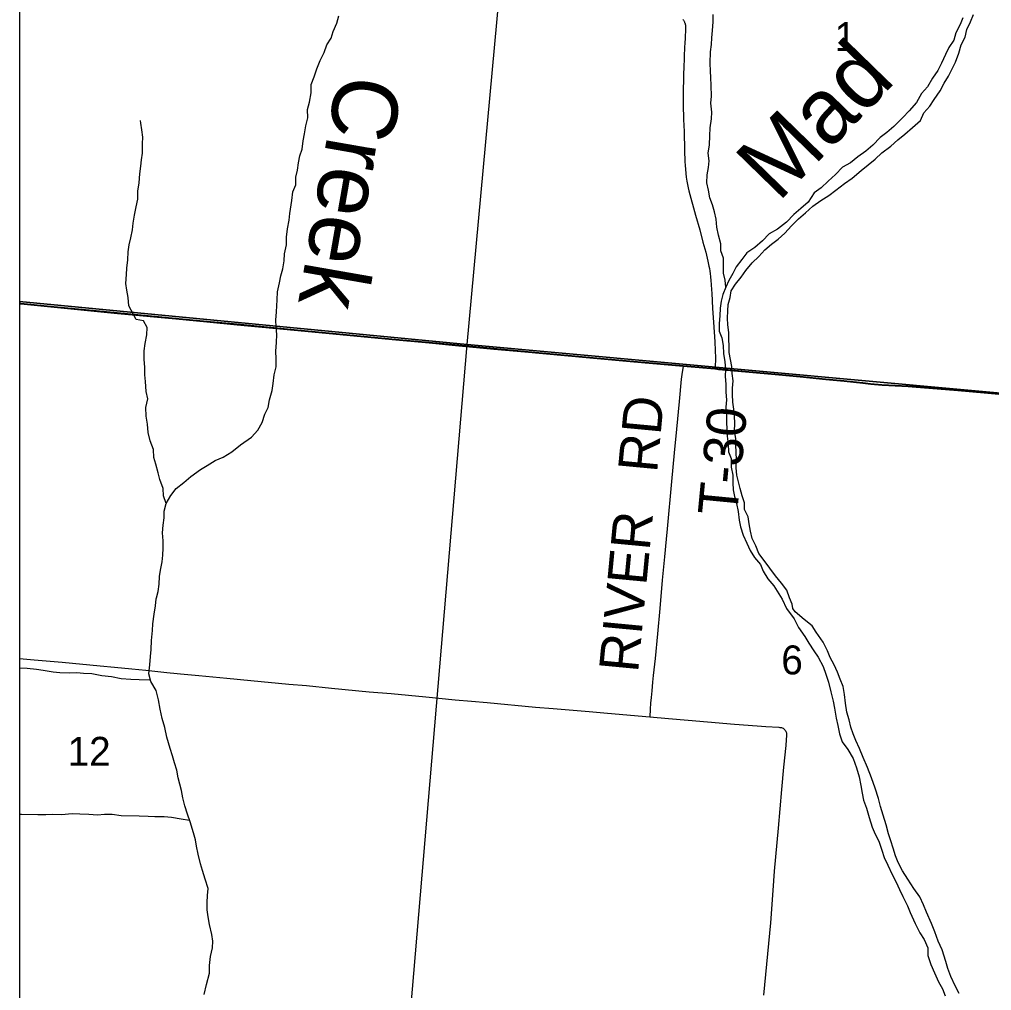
# Model space of a CAD drawing. Extents: x 0 to 1067, y 0 to 440.
# Drawn here: x 798.04 to 799.446, y 352.868 to 354.272 of the extents above; entities that cross this region are included whole.
import ezdxf

# ---------------------------------------------------------------- set-up
doc = ezdxf.new("R2010")
doc.units = 0
for name, color, linetype in [('GM_X_County_Road', 7, 'Continuous'), ('GM_X_Major_River', 7, 'Continuous'), ('GM_X_Major_River_Text', 7, 'Continuous'), ('GM_X_Minor_River', 7, 'Continuous'), ('GM_X_Minor_River_Text', 7, 'Continuous'), ('GM_X_Section', 7, 'Continuous'), ('GM_X_Section_Text', 7, 'Continuous'), ('GM_X_Township_Road', 7, 'Continuous'), ('GM_X_Township_Road_Text', 7, 'Continuous'), ('GM_X_US_Shield', 7, 'Continuous')]:
    doc.layers.add(name, color=color, linetype=linetype)

msp = doc.modelspace()

# ---------------------------------------------------------------- linework, layer by layer
at = {"layer": 'GM_X_County_Road'}
msp.add_line((799.0005, 353.7711), (799.0462, 353.7669), dxfattribs=at)
for points in [[(798.0401, 353.8611), (798.0422, 353.8609), (798.0903, 353.8562), (798.1819, 353.8473), (798.2663, 353.8393), (798.3114, 353.835), (798.3551, 353.8309), (798.4377, 353.8232), (798.5792, 353.8095), (798.6328, 353.8046), (798.6708, 353.8011), (798.7265, 353.7958), (798.7713, 353.7915), (798.8599, 353.7837), (798.9236, 353.7778), (799.0005, 353.7711)], [(799.0462, 353.7669), (799.0514, 353.7664), (799.0903, 353.7628), (799.1386, 353.7583), (799.1695, 353.7554), (799.2066, 353.7518), (799.2331, 353.7491), (799.2604, 353.7462), (799.2719, 353.7448), (799.2881, 353.7435), (799.326, 353.7415), (799.3372, 353.7408), (799.3978, 353.7359), (799.4356, 353.7325), (799.5049, 353.7264), (799.5507, 353.7223), (799.6243, 353.7157), (799.6485, 353.7137), (799.6868, 353.7102), (799.7019, 353.7088)]]:
    msp.add_lwpolyline(points, dxfattribs=at)
at = {"layer": 'GM_X_Major_River'}
for points in [[(799.1588, 353.4205), (799.1579, 353.4267), (799.1542, 353.436), (799.1502, 353.4472), (799.1425, 353.4573), (799.1337, 353.4679), (799.1257, 353.4788), (799.1173, 353.4901), (799.11, 353.5002), (799.1054, 353.5114), (799.1004, 353.5218), (799.0977, 353.5326), (799.0957, 353.5429), (799.0945, 353.5529), (799.0891, 353.5637), (799.089, 353.5736), (799.0859, 353.5836), (799.0828, 353.594), (799.078, 353.6132), (799.0768, 353.6239), (799.0775, 353.6356), (799.0771, 353.6467), (799.0763, 353.6566), (799.0765, 353.6665), (799.0746, 353.6772), (799.0749, 353.6883), (799.0748, 353.6993), (799.0736, 353.7089), (799.072, 353.7188), (799.0716, 353.7299), (799.0715, 353.7394), (799.0725, 353.7497), (799.0713, 353.7604), (799.0709, 353.7707), (799.0669, 353.7906), (799.0668, 353.8001), (799.0663, 353.81), (799.0666, 353.8195), (799.065, 353.8306), (799.0645, 353.8402), (799.0648, 353.8508), (799.0655, 353.8603), (799.0681, 353.8701), (799.0699, 353.88), (799.0759, 353.8897), (799.0841, 353.8997), (799.0912, 353.9094), (799.1003, 353.9206), (799.11, 353.9294), (799.1183, 353.939), (799.128, 353.9475), (799.1377, 353.9548), (799.1474, 353.9633), (799.1569, 353.9737), (799.1674, 353.984), (799.1771, 353.9928), (799.1877, 354.0024), (799.1993, 354.0104), (799.2109, 354.0177), (799.221, 354.0254), (799.2338, 354.0353), (799.245, 354.0426), (799.2579, 354.054), (799.268, 354.062), (799.2781, 354.0705), (799.2878, 354.0793), (799.3006, 354.0892), (799.3111, 354.0984), (799.3212, 354.1065), (799.3321, 354.1161), (799.3435, 354.1264), (799.3487, 354.1373), (799.357, 354.1469), (799.3637, 354.1566), (799.372, 354.1689), (799.378, 354.1802), (799.384, 354.1903), (799.3945, 354.2105), (799.399, 354.2237), (799.4024, 354.2354), (799.4081, 354.2467), (799.4107, 354.258), (799.4159, 354.2689), (799.4204, 354.2794)], [(799.4051, 354.2746), (799.401, 354.2648), (799.395, 354.2532), (799.392, 354.2426), (799.3845, 354.2318), (799.38, 354.2216), (799.374, 354.2092), (799.3687, 354.1984), (799.3612, 354.1875), (799.3536, 354.1748), (799.3453, 354.1652), (799.3378, 354.1521), (799.3272, 354.1402), (799.3182, 354.1306), (799.3049, 354.1173), (799.2951, 354.1088), (799.2854, 354.1015), (799.2745, 354.0904), (799.2644, 354.082), (799.2531, 354.0735), (799.2422, 354.0651), (799.2307, 354.0586), (799.2209, 354.0482), (799.21, 354.0383), (799.1998, 354.0287), (799.1901, 354.0218), (799.1814, 354.0083), (799.1705, 353.9991), (799.1604, 353.9903), (799.1498, 353.9792), (799.137, 353.9689), (799.125, 353.9621), (799.1152, 353.9521), (799.104, 353.9425), (799.0923, 353.9349), (799.0852, 353.9252), (799.077, 353.9148), (799.0721, 353.905), (799.0665, 353.8949), (799.0621, 353.8852), (799.0576, 353.8746), (799.0554, 353.8648), (799.054, 353.855), (799.0533, 353.8436), (799.0522, 353.8329), (799.0526, 353.8215), (799.0565, 353.8118), (799.0581, 353.8008), (799.0589, 353.7893), (799.0608, 353.7771), (799.0616, 353.7664), (799.061, 353.7565), (799.0621, 353.7443), (799.0622, 353.7336), (799.063, 353.7225), (799.0623, 353.7115), (799.0631, 353.6997), (799.0632, 353.6902), (799.0641, 353.6696), (799.0653, 353.6581), (799.0657, 353.647), (799.07, 353.6374), (799.0696, 353.6248), (799.072, 353.6133), (799.0724, 353.6023), (799.0729, 353.5924), (799.0748, 353.5824), (799.0776, 353.5724), (799.0799, 353.5609), (799.0814, 353.5483), (799.0834, 353.5387), (799.0873, 353.5268), (799.0926, 353.5152), (799.0972, 353.5044), (799.1034, 353.4943), (799.1122, 353.4842), (799.1161, 353.4745), (799.123, 353.4636), (799.1314, 353.4535), (799.1438, 353.4341), (799.1499, 353.4206)], [(799.1499, 353.4206), (799.1607, 353.4058), (799.1673, 353.3931), (799.1762, 353.38), (799.1821, 353.3704), (799.1892, 353.3596), (799.1958, 353.35), (799.2028, 353.3369), (799.2068, 353.3258), (799.2104, 353.3143), (799.214, 353.3002), (799.2172, 353.2868), (799.2193, 353.2765), (799.2217, 353.262), (799.2241, 353.2513), (799.2266, 353.2395), (799.2306, 353.228), (799.2384, 353.2169), (799.2461, 353.2038), (799.2512, 353.1904), (799.2548, 353.1774), (799.2572, 353.1648), (799.2593, 353.1534), (799.2614, 353.1434), (799.2654, 353.1319), (799.2693, 353.1186), (799.2736, 353.1044), (799.278, 353.0944), (799.2832, 353.0841), (799.2879, 353.0711), (799.2911, 353.0607), (799.2962, 353.0496), (799.3025, 353.0362), (799.3087, 353.0247), (799.3131, 353.0143), (799.3179, 353.004), (799.3249, 352.9905), (799.3289, 352.981), (799.3362, 352.9652), (799.3428, 352.9518), (799.3491, 352.9418), (799.3542, 352.9299), (799.3544, 352.9189), (799.3588, 352.9059), (799.3639, 352.8936), (799.3697, 352.881), (799.3756, 352.8706), (799.3793, 352.8603)], [(799.1625, 353.4157), (799.1588, 353.4205)], [(799.3995, 352.8641), (799.394, 352.8748), (799.3874, 352.8886), (799.383, 352.9001), (799.3802, 352.9101), (799.3751, 352.9269), (799.3693, 352.9395), (799.3646, 352.9533), (799.3598, 352.9652), (799.3525, 352.9813), (799.3478, 352.992), (799.3426, 353.0035), (799.3341, 353.0155), (799.3256, 353.0293), (799.3178, 353.0412), (799.3116, 353.0535), (799.3075, 353.0631), (799.3043, 353.0742), (799.3007, 353.0845), (799.2975, 353.0949), (799.2939, 353.1079), (799.2896, 353.122), (799.286, 353.1342), (799.2828, 353.1457), (799.2781, 353.1606), (799.273, 353.1759), (799.2672, 353.1905), (799.2606, 353.2051), (799.2555, 353.2181), (799.25, 353.2296), (799.2464, 353.2395), (799.2431, 353.2491), (799.2403, 353.2594), (799.237, 353.2705), (799.2354, 353.2839), (799.2337, 353.2961), (799.2316, 353.3079), (799.2276, 353.3186), (799.2236, 353.3286), (799.2189, 353.3389), (799.213, 353.3497), (799.209, 353.3596), (799.2027, 353.3719), (799.1926, 353.3864), (799.1869, 353.3954), (799.1756, 353.4049), (799.1625, 353.4157)]]:
    msp.add_lwpolyline(points, dxfattribs=at)
at = {"layer": 'GM_X_Minor_River'}
for points in [[(798.2379, 353.4345), (798.2384, 353.4359), (798.2406, 353.4454), (798.2424, 353.456), (798.2427, 353.4667), (798.2441, 353.4762), (798.2464, 353.4883), (798.2474, 353.4978), (798.2481, 353.508), (798.248, 353.5183), (798.2472, 353.5301), (798.2479, 353.5412), (798.2494, 353.5518), (798.2493, 353.5613), (798.2523, 353.5726), (798.259, 353.5839), (798.2669, 353.5943), (798.2778, 353.6027), (798.2879, 353.6115), (798.3019, 353.6214), (798.3119, 353.6272), (798.3235, 353.6348), (798.3347, 353.6394), (798.3474, 353.6471), (798.3599, 353.6573), (798.3757, 353.6683), (798.3851, 353.6786), (798.3915, 353.6895), (798.3949, 353.7016), (798.3998, 353.7113), (798.402, 353.7223), (798.4058, 353.7359), (798.4072, 353.7461), (798.4087, 353.7583), (798.4113, 353.77), (798.4117, 353.7814), (798.4112, 353.7925), (798.412, 353.8054), (798.4123, 353.8168), (798.4115, 353.8279), (798.411, 353.8374), (798.4118, 353.8496), (798.413, 353.8671), (798.4137, 353.8785), (798.4164, 353.8913), (798.4182, 353.9015), (798.4212, 353.9117), (798.423, 353.9231), (798.4237, 353.9334), (798.4263, 353.9462), (798.4267, 353.9576), (798.4278, 353.9694), (798.4304, 353.9823), (798.4315, 353.9918), (798.4343, 354.0103), (798.4358, 354.0232), (798.4399, 354.033), (798.4402, 354.0444), (798.4424, 354.0546), (798.4438, 354.0649), (798.4457, 354.0751), (798.449, 354.0849), (798.4508, 354.0967), (798.4527, 354.1069), (798.4545, 354.1186), (798.4575, 354.1303), (798.4571, 354.1422), (798.4597, 354.1527), (798.462, 354.1664), (798.4623, 354.1785), (798.4665, 354.1895), (798.4702, 354.2011), (798.4751, 354.2128), (798.4808, 354.2244), (798.4849, 354.2354), (798.4909, 354.2451), (798.4942, 354.2549), (798.4991, 354.2669), (798.5024, 354.2775)], [(799.0621, 353.8852), (799.0612, 353.8951), (799.0585, 353.9055), (799.0588, 353.9165), (799.0587, 353.9272), (799.0549, 353.9379), (799.0548, 353.9478), (799.0514, 353.9605), (799.049, 353.972), (799.0479, 353.9835), (799.0455, 353.9942), (799.0428, 354.0042), (799.0389, 354.0146), (799.0369, 354.0253), (799.0346, 354.036), (799.0353, 354.0478), (799.0368, 354.0584), (799.0378, 354.0679), (799.0366, 354.079), (799.0385, 354.0911), (799.0389, 354.1041), (799.0396, 354.1155), (799.0411, 354.1288), (799.0417, 354.1383), (799.0406, 354.1512), (799.0413, 354.1615), (799.041, 354.1767), (799.0405, 354.1882), (799.0401, 354.1977), (799.0393, 354.2092), (799.0401, 354.2255), (799.0412, 354.2361), (799.0418, 354.2456), (799.0429, 354.2563), (799.0437, 354.2688), (799.0436, 354.2795)], [(798.2523, 353.5726), (798.2484, 353.5834), (798.248, 353.5941), (798.243, 353.6072), (798.2407, 353.6168), (798.2376, 353.6294), (798.2345, 353.6391), (798.234, 353.6505), (798.2291, 353.6632), (798.2264, 353.6751), (798.2256, 353.6873), (798.2237, 353.6988), (798.2229, 353.711), (798.2259, 353.7239), (798.2236, 353.7346), (798.2225, 353.7487), (798.2213, 353.7583), (798.2216, 353.7697), (798.2204, 353.7808), (798.2204, 353.7933), (798.2222, 353.8036), (798.2245, 353.8161), (798.2248, 353.8267), (798.2197, 353.8364), (798.2092, 353.8386), (798.1984, 353.858), (798.1976, 353.8702), (798.1956, 353.8809), (798.194, 353.8905), (798.1951, 353.9034), (798.1954, 353.9129), (798.1969, 353.9247), (798.1972, 353.9365), (798.1987, 353.9463), (798.2012, 353.9565), (798.2035, 353.9679), (798.2045, 353.9777), (798.2064, 353.9891), (798.209, 354.0012), (798.2112, 354.0126), (798.2112, 354.024), (798.2134, 354.0361), (798.2142, 354.049), (798.2156, 354.06), (798.2167, 354.0695), (798.2181, 354.079), (798.2181, 354.0923), (798.2188, 354.1022), (798.2172, 354.1129), (798.2156, 354.1225), (798.2153, 354.1263)], [(798.2328, 353.3889), (798.2333, 353.3984), (798.2351, 353.4124), (798.2368, 353.4245), (798.2379, 353.4345)], [(798.3074, 352.8624), (798.3107, 352.8771), (798.3151, 352.8934), (798.3153, 352.9044), (798.3163, 352.9173), (798.3192, 352.9298), (798.3198, 352.9396), (798.3184, 352.9491), (798.3149, 352.9636), (798.3132, 352.9747), (798.3118, 352.985), (798.3116, 352.9956), (798.3122, 353.0058), (798.3131, 353.0157), (798.3088, 353.0294), (798.3049, 353.0417), (798.302, 353.0516), (798.2988, 353.0653), (798.2964, 353.0768), (798.2946, 353.0863), (798.2918, 353.0962), (798.2871, 353.1119), (798.2831, 353.1233), (798.2792, 353.1352), (798.2767, 353.147), (798.2746, 353.1576), (798.27, 353.1756), (798.2679, 353.1866), (798.2643, 353.1973), (798.2618, 353.2076), (798.2582, 353.2183), (798.2532, 353.2347), (798.2504, 353.2484), (798.2468, 353.2614), (798.2437, 353.2751), (798.2413, 353.2885), (798.2377, 353.3018), (798.2303, 353.3149), (798.2275, 353.3263), (798.2289, 353.3392), (798.2298, 353.3513), (798.2308, 353.3612), (798.2314, 353.3741), (798.2328, 353.3889)], [(798.2299, 353.3168), (798.2133, 353.3174), (798.2012, 353.318), (798.1875, 353.319), (798.1735, 353.3216), (798.1591, 353.323), (798.1447, 353.3259), (798.133, 353.3268), (798.1231, 353.3274), (798.1125, 353.3272), (798.0988, 353.3274), (798.089, 353.3287), (798.0746, 353.3309), (798.0648, 353.3326), (798.0515, 353.3336), (798.0401, 353.3344)], [(798.2863, 353.1142), (798.2743, 353.1159), (798.2603, 353.1184), (798.2497, 353.1193), (798.236, 353.1192), (798.2265, 353.1198), (798.2132, 353.1204), (798.1874, 353.1208), (798.1742, 353.1226), (798.1632, 353.1228), (798.1533, 353.1218), (798.1404, 353.1228), (798.1275, 353.1234), (798.1165, 353.1236), (798.1009, 353.1223), (798.0884, 353.1225), (798.0782, 353.1223), (798.0668, 353.1222), (798.0429, 353.1226), (798.0401, 353.1229)]]:
    msp.add_lwpolyline(points, dxfattribs=at)
at = {"layer": 'GM_X_Section'}
for points in [[(798.781, 354.8126), (799.7802, 354.7186), (799.6925, 353.7106), (798.688, 353.8024)], [(798.688, 353.8024), (799.6925, 353.7106), (799.6121, 352.7044), (798.6013, 352.7849)]]:
    msp.add_lwpolyline(points, close=True, dxfattribs=at)
at = {"layer": 'GM_X_Township_Road'}
msp.add_line((799.0462, 353.7669), (799.0005, 353.7711), dxfattribs=at)
for points in [[(798.0401, 357.6021), (798.0401, 353.8616), (798.042, 353.8615), (798.0901, 353.8568), (798.1817, 353.8479), (798.2661, 353.8398), (798.3111, 353.8356), (798.3549, 353.8315), (798.4375, 353.8237), (798.5789, 353.8101), (798.6326, 353.8052), (798.6706, 353.8016), (798.7262, 353.7963), (798.771, 353.7921), (798.8597, 353.7842), (798.9234, 353.7784), (799.0003, 353.7716), (799.0459, 353.7674), (799.0512, 353.7669), (799.0901, 353.7633), (799.1383, 353.7588), (799.1693, 353.756), (799.2063, 353.7523), (799.2329, 353.7496), (799.2601, 353.7467), (799.2716, 353.7454), (799.2879, 353.7441), (799.3258, 353.742), (799.3369, 353.7414), (799.3976, 353.7364), (799.4354, 353.7331), (799.5047, 353.7269)], [(798.9997, 354.2723), (799.0003, 354.2718), (799.0008, 354.2712), (799.0013, 354.2705), (799.0017, 354.2698), (799.0021, 354.269), (799.0025, 354.2681), (799.0028, 354.2672), (799.0032, 354.2662), (799.0034, 354.2653), (799.0036, 354.2641), (799.0036, 354.263), (799.0037, 354.2618), (799.0038, 354.2591), (799.0037, 354.2553), (799.0034, 354.2487), (799.0032, 354.2439), (799.0029, 354.2396), (799.0024, 354.231), (799.0019, 354.2201), (799.0017, 354.214), (799.0014, 354.2054), (799.0009, 354.1913), (799.0006, 354.1821), (799.0004, 354.1741), (799.0003, 354.1649), (799.0004, 354.1494), (799.0009, 354.1277), (799.0016, 354.1103), (799.0024, 354.083), (799.0029, 354.0668), (799.0033, 354.0613), (799.0037, 354.0557), (799.0043, 354.0498), (799.0049, 354.0445), (799.0058, 354.0387), (799.0067, 354.0335), (799.0077, 354.0288), (799.0087, 354.0244), (799.0184, 353.9894), (799.0244, 353.9679), (799.0289, 353.9505), (799.033, 353.9358), (799.036, 353.923), (799.0366, 353.9203), (799.0377, 353.9154), (799.0384, 353.912), (799.0391, 353.9085), (799.0396, 353.9048), (799.0401, 353.9), (799.0405, 353.8949), (799.0409, 353.8892), (799.0414, 353.8814), (799.0416, 353.8766), (799.0428, 353.8546), (799.0441, 353.8345), (799.046, 353.8064), (799.0464, 353.7938), (799.0469, 353.783), (799.047, 353.7805), (799.0469, 353.7772), (799.0467, 353.7744), (799.0465, 353.7721), (799.0464, 353.7698), (799.0462, 353.7669)], [(799.5047, 353.7269), (799.4354, 353.7331), (799.3976, 353.7364), (799.3369, 353.7414), (799.3258, 353.742), (799.2879, 353.7441), (799.2716, 353.7454), (799.2601, 353.7467), (799.2329, 353.7496), (799.2063, 353.7523), (799.1693, 353.756), (799.1383, 353.7588), (799.0901, 353.7633), (799.0512, 353.7669), (799.0459, 353.7674), (799.0003, 353.7716), (798.9234, 353.7784), (798.8597, 353.7842), (798.771, 353.7921), (798.7262, 353.7963), (798.6706, 353.8016), (798.6326, 353.8052), (798.5789, 353.8101), (798.4375, 353.8237), (798.3549, 353.8315), (798.3111, 353.8356), (798.2661, 353.8398), (798.1817, 353.8479), (798.0901, 353.8568), (798.042, 353.8615), (798.0401, 353.8616), (798.0401, 350.8021)], [(799.0005, 353.7711), (798.9986, 353.759), (798.9976, 353.7522), (798.9944, 353.7201), (798.9905, 353.6799), (798.9873, 353.6458), (798.9835, 353.6044), (798.9771, 353.5357), (798.9756, 353.5209), (798.9732, 353.4955), (798.9701, 353.4615), (798.9664, 353.4206), (798.9631, 353.3841), (798.9596, 353.3483), (798.9569, 353.3236), (798.956, 353.3143), (798.9549, 353.3017), (798.9541, 353.2921), (798.9533, 353.2837), (798.9528, 353.275), (798.952, 353.2641)], [(798.0401, 353.3485), (798.0612, 353.3466), (798.1021, 353.3429), (798.1571, 353.3376), (798.1775, 353.3356), (798.2025, 353.3332), (798.223, 353.3312), (798.2536, 353.3281), (798.2681, 353.3267)], [(798.2681, 353.3267), (798.2729, 353.3263), (798.2998, 353.3239), (798.3402, 353.32), (798.3747, 353.3167), (798.4298, 353.3114), (798.4552, 353.3091), (798.4917, 353.3056), (798.5461, 353.3003), (798.5777, 353.2975), (798.6279, 353.2928), (798.6705, 353.2887), (798.694, 353.2867), (798.7169, 353.2846), (798.7868, 353.2781), (798.8122, 353.2761), (798.8643, 353.2715), (798.8855, 353.2696), (798.9131, 353.2673), (798.952, 353.2641)], [(798.952, 353.2641), (798.9789, 353.2616), (799.0076, 353.259), (799.0355, 353.2567), (799.0745, 353.2534), (799.1072, 353.251), (799.1199, 353.25), (799.1387, 353.2489), (799.1401, 353.2487), (799.1415, 353.2486), (799.1427, 353.2483), (799.1437, 353.248), (799.145, 353.2474), (799.1459, 353.2467), (799.1466, 353.2461), (799.1473, 353.2453), (799.148, 353.2444), (799.1487, 353.2433), (799.1492, 353.242), (799.1496, 353.2407), (799.1499, 353.2393), (799.15, 353.237), (799.1495, 353.2306), (799.1488, 353.2225), (799.1457, 353.191), (799.1426, 353.1588), (799.1378, 353.1031), (799.1322, 353.0406), (799.1301, 353.0127), (799.1265, 352.9662), (799.1168, 352.8617)]]:
    msp.add_lwpolyline(points, dxfattribs=at)
at = {"layer": 'GM_X_US_Shield'}
for points in [[(798.0401, 354.8762), (798.0401, 353.8646), (798.688, 353.8024), (798.781, 354.8126)], [(798.0401, 353.8646), (798.0401, 352.8335), (798.6013, 352.7849), (798.688, 353.8024)]]:
    msp.add_lwpolyline(points, close=True, dxfattribs=at)

# ---------------------------------------------------------------- texts
at = {"layer": 'GM_X_Major_River_Text'}
msp.add_text('Mad', height=0.09465, rotation=45.7783, dxfattribs=at).set_placement((799.1377, 354.0067))
at = {"layer": 'GM_X_Minor_River_Text'}
msp.add_text('Creek', height=0.09465, rotation=260.0852, dxfattribs=at).set_placement((798.5015, 354.1962))
at = {"layer": 'GM_X_Section_Text'}
for s, height, p in [('1', 0.0419, (799.2194, 354.2266)), ('6', 0.0419, (799.1423, 353.3253)), ('12', 0.04186, (798.1098, 353.1931))]:
    msp.add_text(s, height=height, rotation=0, dxfattribs=at).set_placement(p)
at = {"layer": 'GM_X_Township_Road_Text'}
for s, rotation, p in [('RD', 84.6287, (798.9625, 353.6159)), ('T-30', 84.5036, (799.078, 353.5532)), ('RIVER', 84.5789, (798.935, 353.3269))]:
    msp.add_text(s, height=0.05682, rotation=rotation, dxfattribs=at).set_placement(p)

doc.saveas('drawing.dxf')
